(* Logix 5000 project; controller Electronic_Displays vendor 1 type 14 code 65 rev 17.4; software revision 17.01; part 8 of 8 *)
(* tags used below, declared in another part *)
   SEQ : DINT;
   SEQ_TImer : TIMER[20];
   Sign03_Erase : ResetSign;
   Sign03_Setup : SetupSignVariables;
   Sign03M1 : LEDSIGN;
   Sign03M2 : LEDSIGN;
   Tag_Sign03M1 : SendSignMessage;
   Tag_Sign03M2 : SendSignMessage;
   TogglesSign3 : DINT;
(* MainProgram, continued *)

ROUTINE R03Sign03   (* ladder *)
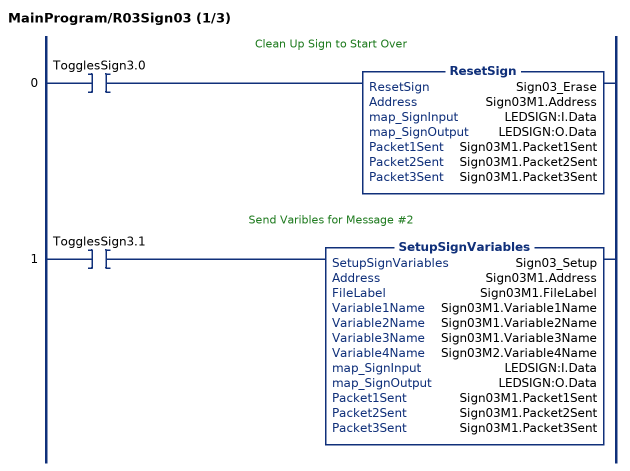
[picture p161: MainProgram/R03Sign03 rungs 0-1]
   // Clean Up Sign to Start Over
   0: XIC(TogglesSign3.0)ResetSign(Sign03_Erase,Sign03M1.Address,LEDSIGN:I.Data,LEDSIGN:O.Data,Sign03M1.Packet1Sent,Sign03M1.Packet2Sent,Sign03M1.Packet3Sent);
   // Send Varibles for Message #2
   1: XIC(TogglesSign3.1)SetupSignVariables(Sign03_Setup,Sign03M1.Address,Sign03M1.FileLabel,Sign03M1.Variable1Name,Sign03M1.Variable2Name,Sign03M1.Variable3Name,Sign03M2.Variable4Name,LEDSIGN:I.Data,LEDSIGN:O.Data,Sign03M1.Packet1Sent,Sign03M1.Packet2Sent,Sign03M1.Packet3Sent);
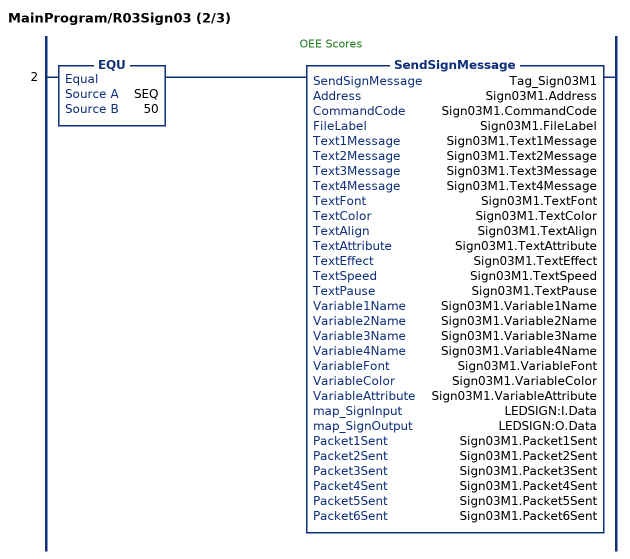
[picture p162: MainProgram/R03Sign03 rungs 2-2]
   // OEE Scores
   2: EQU(SEQ,50)SendSignMessage(Tag_Sign03M1,Sign03M1.Address,Sign03M1.CommandCode,Sign03M1.FileLabel,Sign03M1.Text1Message,Sign03M1.Text2Message,Sign03M1.Text3Message,Sign03M1.Text4Message,Sign03M1.TextFont,Sign03M1.TextColor,Sign03M1.TextAlign,Sign03M1.TextAttribute,Sign03M1.TextEffect,Sign03M1.TextSpeed,Sign03M1.TextPause,Sign03M1.Variable1Name,Sign03M1.Variable2Name,Sign03M1.Variable3Name,Sign03M1.Variable4Name,Sign03M1.VariableFont,Sign03M1.VariableColor,Sign03M1.VariableAttribute,LEDSIGN:I.Data,LEDSIGN:O.Data,Sign03M1.Packet1Sent,Sign03M1.Packet2Sent,Sign03M1.Packet3Sent,Sign03M1.Packet4Sent,Sign03M1.Packet5Sent,Sign03M1.Packet6Sent);
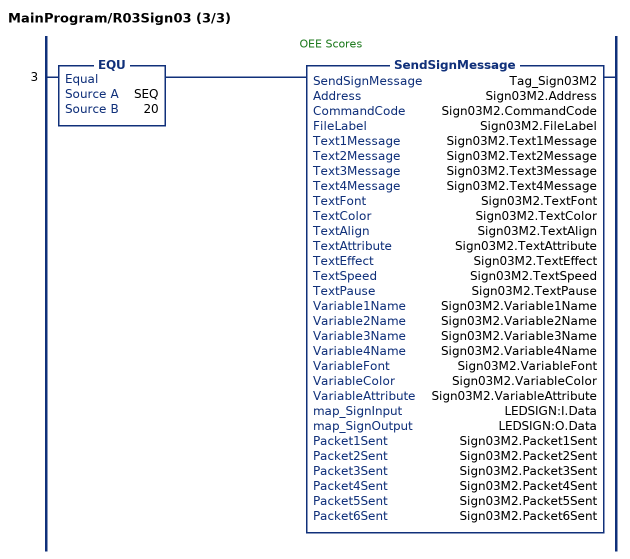
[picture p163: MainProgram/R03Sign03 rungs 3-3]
   // OEE Scores
   3: EQU(SEQ,20)SendSignMessage(Tag_Sign03M2,Sign03M2.Address,Sign03M2.CommandCode,Sign03M2.FileLabel,Sign03M2.Text1Message,Sign03M2.Text2Message,Sign03M2.Text3Message,Sign03M2.Text4Message,Sign03M2.TextFont,Sign03M2.TextColor,Sign03M2.TextAlign,Sign03M2.TextAttribute,Sign03M2.TextEffect,Sign03M2.TextSpeed,Sign03M2.TextPause,Sign03M2.Variable1Name,Sign03M2.Variable2Name,Sign03M2.Variable3Name,Sign03M2.Variable4Name,Sign03M2.VariableFont,Sign03M2.VariableColor,Sign03M2.VariableAttribute,LEDSIGN:I.Data,LEDSIGN:O.Data,Sign03M2.Packet1Sent,Sign03M2.Packet2Sent,Sign03M2.Packet3Sent,Sign03M2.Packet4Sent,Sign03M2.Packet5Sent,Sign03M2.Packet6Sent);
END_ROUTINE

ROUTINE R04Seq   (* ladder *)
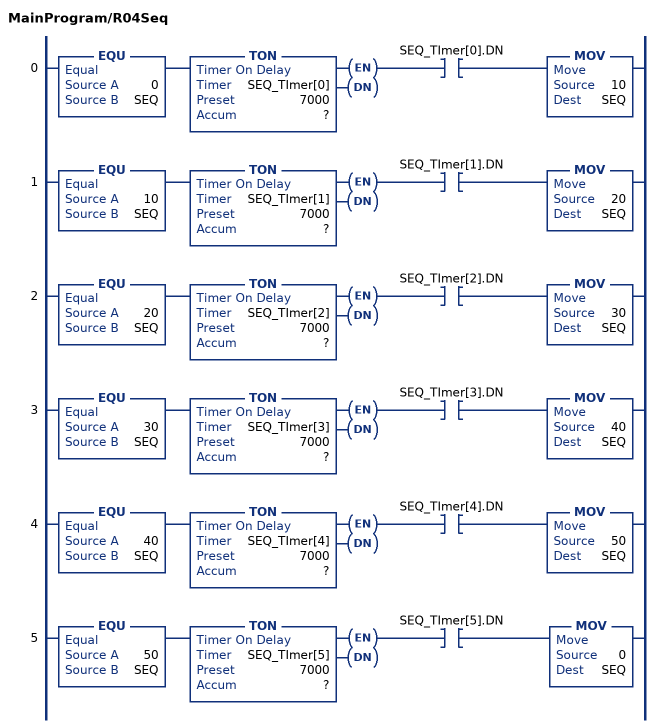
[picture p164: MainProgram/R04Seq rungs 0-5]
   0: EQU(0,SEQ)TON(SEQ_TImer[0],?,?)XIC(SEQ_TImer[0].DN)MOV(10,SEQ);
   1: EQU(10,SEQ)TON(SEQ_TImer[1],?,?)XIC(SEQ_TImer[1].DN)MOV(20,SEQ);
   2: EQU(20,SEQ)TON(SEQ_TImer[2],?,?)XIC(SEQ_TImer[2].DN)MOV(30,SEQ);
   3: EQU(30,SEQ)TON(SEQ_TImer[3],?,?)XIC(SEQ_TImer[3].DN)MOV(40,SEQ);
   4: EQU(40,SEQ)TON(SEQ_TImer[4],?,?)XIC(SEQ_TImer[4].DN)MOV(50,SEQ);
   5: EQU(50,SEQ)TON(SEQ_TImer[5],?,?)XIC(SEQ_TImer[5].DN)MOV(0,SEQ);
END_ROUTINE
END_PROGRAM
